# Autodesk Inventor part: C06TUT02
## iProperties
Created: 2009-04
Part Number: C06TUT02
Document SubType Name: Modeling
Designer: Sham
Density: 1 g/cm^3
Author: Sham
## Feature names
1. Extrusion1
2. Hole1
3. Hole2
4. Hole3
5. Hole4
6. Extrusion2
7. Extrusion3
8. Extrusion4
9. Extrusion5
10. Hole5
11. Hole6
12. Hole7
13. Hole8
14. Hole9
15. Fillet1
